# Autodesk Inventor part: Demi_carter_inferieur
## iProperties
Shininess: 64.0
Length Units: 11269
Angle Units: 11279
Time Units: 11290
Mass Units: 11283
Length Display Precision: 3
Angle Display Precision: 2
Compacted: True
Part Number: Demi_carter_inferieur
Document SubType Name: Sheet Metal
Created: 2008-02
Material: Acier doux
Designer: Pascal
Density: 0.0
Volumn: 0.0
Area: 0.0
PropertySet Name: Model Information
Control State: 0
Master: False
Checked Out: False
DESIGNATION: Demi-carter inférieur
OBSERVATIONS: Tôle ep 15/10
MATIERE_PIECE: X2CrNi 18-11
Author: Pascal
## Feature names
1. Plaque1
2. Pli1
